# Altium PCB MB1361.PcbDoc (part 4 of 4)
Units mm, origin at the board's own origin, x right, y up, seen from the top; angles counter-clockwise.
Board outline 70 x 133.34 mm, 6 copper layers (Top Layer, Signal Layer 1, Signal Layer 2, Signal Layer 3, Signal Layer 4, Bottom Layer), stack 1.578 mm thick; 268 components, 251 nets, 1066 pads, 705 vias.
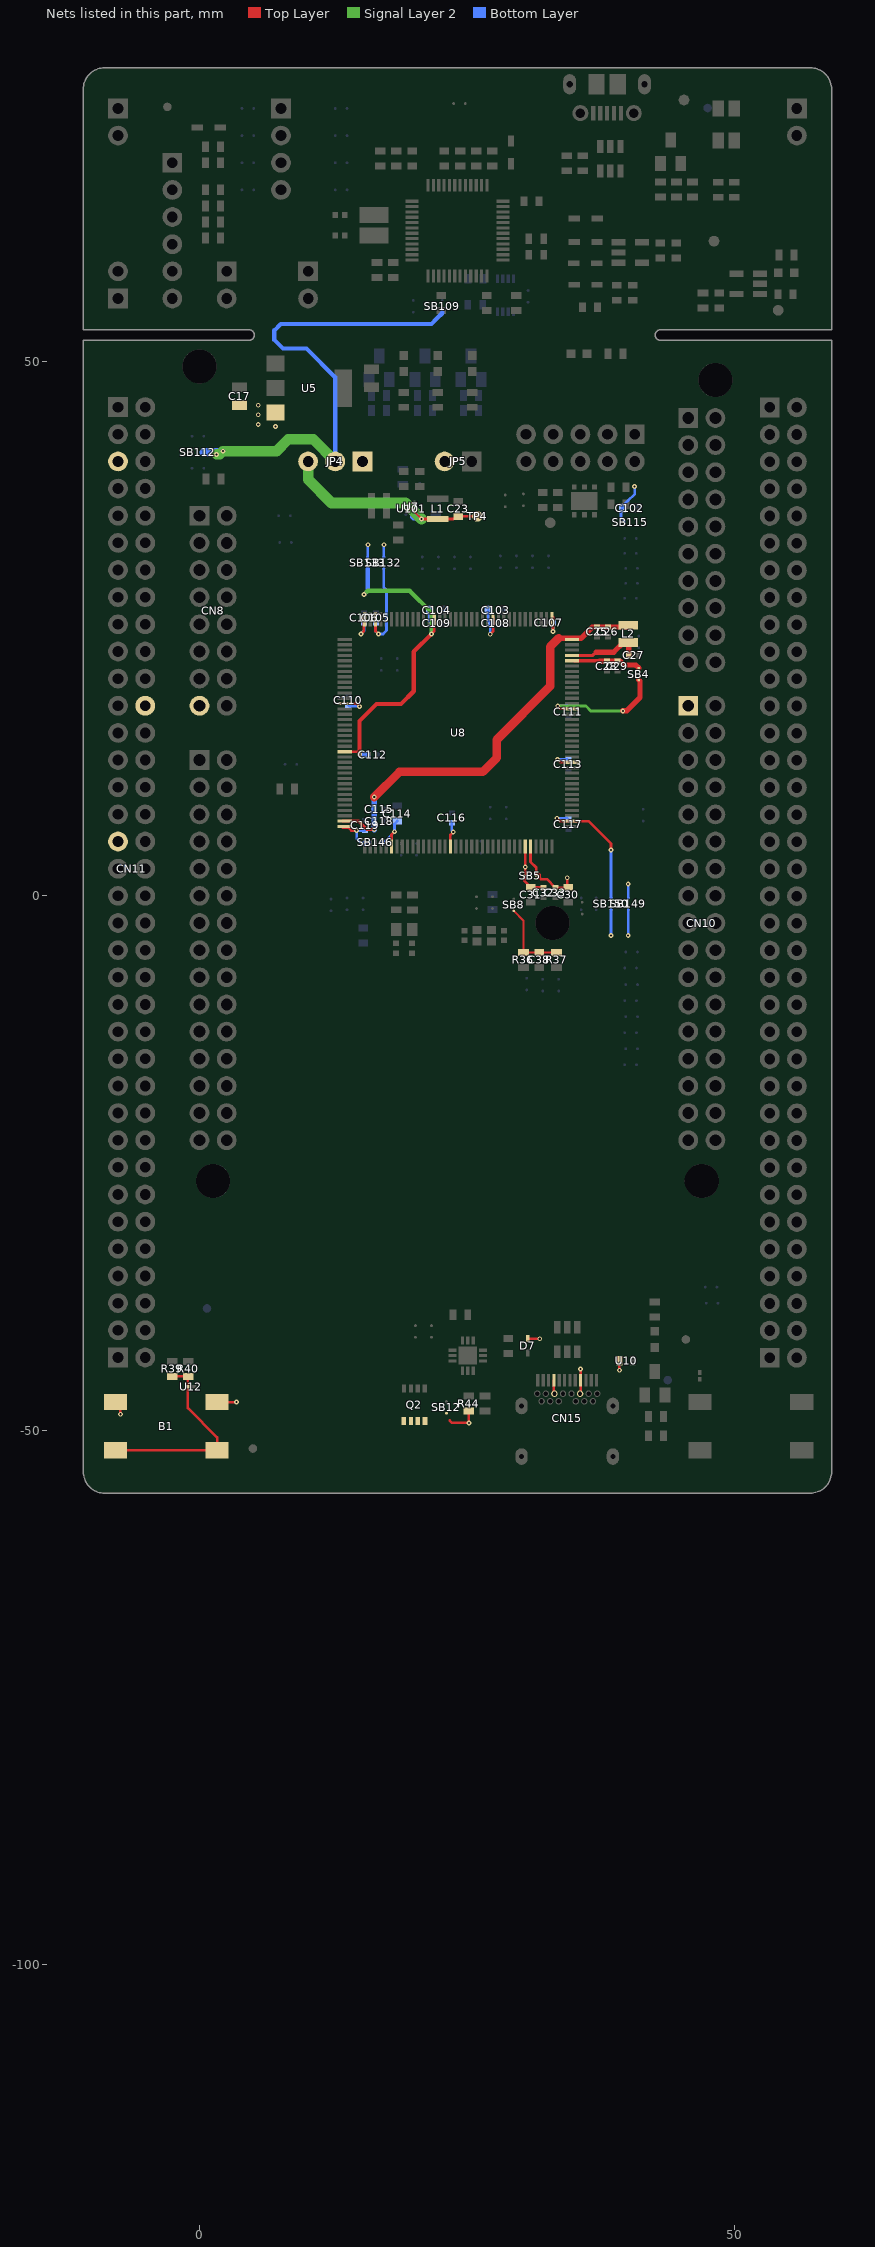
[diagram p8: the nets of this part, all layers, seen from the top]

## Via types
v1: diameter 0.45, hole 0.2, Top Layer to Bottom Layer, tented both sides, 705 vias

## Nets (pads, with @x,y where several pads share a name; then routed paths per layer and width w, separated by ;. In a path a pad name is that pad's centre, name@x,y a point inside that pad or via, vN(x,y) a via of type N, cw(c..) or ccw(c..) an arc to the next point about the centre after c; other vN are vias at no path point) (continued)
USER_BUTTON: B1.3 B1.4 R39.2 R40.2 U12.1 | length 19
  Top Layer w0.25: B1.3@-7.849,-51.856 B1.4@1.651,-51.856 1.651,-50.651 -1.087,-47.913 -1.087,-45.9 -1.087,-44.987 R40.2@-1.05,-44.95 -2.537,-44.95 R39.2@-2.54,-44.947
V15_COUT: C25.2 C26.2 C115.2 C118.2 L2.1 U8.72 U8.143 | length 39.9
  Top Layer w0.3: U8.143@13.392,6.99 U8.143@13.592,6.99 14.91,6.99 15.7,6.2 v1(16.35,6.2)
  Top Layer w0.5: 33.59,24.09 35.69,24.09 36.75,25.15 C25.2@37.2,25.15 C26.2@38.2,25.15 40,25.15 L2.1@40.1,25.25
  Top Layer w0.8: v1(16.35,9.25) 18.7,11.6 26.5,11.6 27.8,12.9 27.8,14.6 32.8,19.6 32.8,23.3 33.59,24.09
  Bottom Layer w0.5: v1(16.35,6.2) C118.2@16.35,7 C115.2@16.35,8.1 v1(16.35,9.25)
VBAT: C114.2 CN11.33 SB146.2 U8.6 | length 4.5
  Top Layer w0.25: U8.6@17.967,4.44 17.967,5.738 v1(18.234,6.005)
  Bottom Layer w0.127: SB146.2@17,5 17.3,5
  Bottom Layer w0.2: 17.3,5 17.3,5.071 v1(18.234,6.005)
  Bottom Layer w0.25: v1(18.234,6.005) 18.234,6.734 C114.2@18.5,7
VBUS_SENSE: C38.2 R36.2 R37.1 SB8.2 | length 7.4
  Top Layer w0.2: SB8.2@29.4,-1.4 30.3,-2.3 R36.2@30.3,-5.3 C38.2@31.8,-5.3 R37.1@33.4,-5.3
VBUSc: CN15.A4 CN15.A9 CN15.B4 CN15.B9 D7.1 Q2.5 Q2.6 Q2.7 Q2.8 R44.2 SB12.2 U10.1 | length 8.6
  Top Layer w0.25: 23.4,-49.075 23.625,-49.3 v1(25.2,-49.3) R44.2@25.2,-48.2 ; D7.1@30.7,-41.425 v1(31.825,-41.425) ; CN15.A4@33.15,-45.32 33.15,-46.52 CN15.B9@33.2,-46.57 ; CN15.B4@35.6,-46.57 35.65,-46.52 CN15.A9@35.65,-45.32 v1(35.65,-44.25) ; v1(39.275,-44.375) U10.1@39.275,-43.5
VDD: CN11.5 JP4.1 JP5.2 SB132.1 SB133.1 SB149.1 | length 3.6
  Bottom Layer w0.25: SB133.1@15.75,31.7 v1(15.75,32.85) ; SB132.1@17.25,31.7 v1(17.25,32.85) ; SB149.1@40.1,-0.2 v1(40.1,1.1)
VDD_MCU: B1.1 B1.2 C103.2 C106.2 C107.2 C108.2 C110.2 C111.2 C113.2 C116.2 C117.2 C119.2 JP4.2 SB4.1 SB109.2 SB112.1 SB146.1 SB150.1 U8.17 U8.38 U8.49 U8.59 U8.73 U8.84 U8.108 U8.121 U8.144 | length 96.2
  Top Layer w0.25: B1.1@-7.849,-47.356 -7.4,-47.805 v1(-7.4,-48.5) ; B1.2@1.651,-47.356 v1(3.446,-47.356) ; U8.144@13.392,6.39 13.927,6.39 14.217,6.1 v1(14.7,6.1) ; U8.121@13.392,17.99 U8.121@13.592,17.99 14.69,17.99 v1(14.957,17.723) ; v1(15.1,24.5) 15.367,24.767 U8.108@15.367,26.065 ; U8.17@23.467,4.415 U8.17@23.467,4.615 23.467,5.713 v1(23.734,5.98) ; v1(27.2,24.475) 27.467,24.742 U8.84@27.467,26.04 ; v1(33.067,24.733) U8.73@33.067,26.065 ; v1(33.452,7.257) 33.719,6.99 U8.38@35.017,6.99 ; v1(33.492,12.757) 33.759,12.49 U8.49@35.057,12.49 ; v1(33.517,17.757) 33.784,17.49 U8.59@34.842,17.49 U8.59@35.082,17.49 ; U8.38@35.042,6.99 36.41,6.99 38.5,4.9 v1(38.5,4.3)
  Top Layer w0.5: v1(39.6,17.3) 39.951,17.3 41.202,18.551 41.202,20.098 SB4.1@41.1,20.2
  Signal Layer 2 w0.25: v1(33.517,17.757) 36.143,17.757 36.6,17.3 v1(39.6,17.3)
  Signal Layer 2 w1: v1(1.6,41.3) 1.9,41.3 v1(2.2,41.6) 7.2,41.6 8.3,42.7 10.64,42.7 JP4.2@12.7,40.64
  Bottom Layer w0.25: C110.2@13.9,17.85 14.027,17.723 v1(14.957,17.723) ; v1(15.1,24.5) 15.4,24.8 C106.2@15.4,25.55 ; C119.2@15.5,6.15 15.45,6.1 v1(14.7,6.1) 14.7,5.357 15.057,5 SB146.1@15.9,5 ; C116.2@23.6,6.85 23.6,6.114 v1(23.734,5.98) ; C103.2@27,26.7 27,25.75 C108.2@27.25,25.5 27.2,25.45 v1(27.2,24.475) ; v1(33.067,24.733) 33.067,25.524 C107.2@33.098,25.555 ; v1(33.452,7.257) 34.393,7.257 C117.2@34.5,7.15 ; v1(33.492,12.757) 34.393,12.757 C113.2@34.5,12.65 ; v1(33.517,17.757) 34.393,17.757 C111.2@34.5,17.65 ; SB150.1@38.5,-0.2 v1(38.5,4.3)
  Bottom Layer w0.4: JP4.2@12.7,40.64 12.7,48.5 10,51.2 7.8,51.2 7,52 7,52.9 7.6,53.5 21.7,53.5 22.2,54 22.7,54.5 SB109.2@22.7,54.6
  Bottom Layer w0.8: SB112.1@0.4,41.5 v1@2.1,41.5
VDD_SMPS_1V8: C23.2 JP4.3 L1.2 TP4.1 U7.E3 U101.C2 | length 21.5
  Top Layer w0.152: L1.2@22.097,35.357 22.145,35.405 L1.2@22.181,35.44
  Top Layer w0.2: U7.E3@20.124,35.9 v1(20.774,35.25)
  Top Layer w0.25: v1(20.774,35.25) L1.2@22.3,35.25 23.75,35.25 24,35.5 C23.2@24.2,35.5 TP4.1@26,35.5
  Signal Layer 2 w1: JP4.3@10.16,40.64 10.16,38.94 12.352,36.748 19.276,36.748 v1(20.774,35.25)
  Bottom Layer w0.25: U101.C2@19.8,35.7 19.8,35.425 19.975,35.25 v1(20.774,35.25)
VDD_USB: C105.2 SB132.2 U8.106 | length 9.6
  Top Layer w0.25: U8.106@16.467,26.065 U8.106@16.467,25.865 16.467,24.767 v1(16.734,24.5)
  Bottom Layer w0.25: C105.2@16.5,25.55 16.5,24.734 v1(16.734,24.5) 17.181,24.5 17.5,24.819 17.5,28.6 17.25,28.85 SB132.2@17.25,30.6
VDDA: C30.1 C33.2 CN10.1 SB5.1 SB149.2 SB150.2 U8.32 | length 11.9
  Top Layer w0.25: U8.32@30.967,4.415 30.967,3.172 31.5,2.639 SB5.1@31.5,1.9 ; 31.8,2 31.8,1.7 31.937,1.562 32.487,1.562 C33.2@33.3,0.75 34.45,0.75 C30.1@34.5,0.8 34.4,0.9 v1(34.4,1.7)
  Bottom Layer w0.25: v1(38.5,-3.7) SB150.2@38.5,-1.3 ; v1(40.1,-3.7) SB149.2@40.1,-1.3
VDDIO: C104.2 C109.2 C112.2 SB133.2 U8.95 U8.130 | length 33.6
  Top Layer w0.25: U8.130@13.392,13.49 U8.130@13.592,13.49 14.957,13.49 ; v1(21.7,24.5) 21.967,24.767 U8.95@21.967,25.865 U8.95@21.967,26.065
  Top Layer w0.4: v1(14.957,13.223) 14.957,13.49 14.957,16.357 16.554,17.954 18.854,17.954 20.046,19.146 20.046,22.846 v1(21.7,24.5)
  Signal Layer 2 w0.4: v1(15.4,28.2) 15.744,28.544 19.656,28.544 21.7,26.5 v1(21.7,24.5)
  Bottom Layer w0.25: C104.2@21.5,26.7 21.5,25.75 C109.2@21.75,25.5 21.7,25.45 v1(21.7,24.5)
  Bottom Layer w0.4: v1(14.957,13.223) 15.727,13.223 C112.2@15.75,13.2 ; v1(15.4,28.2) 15.75,28.55 SB133.2@15.75,30.6
VDDSMPS_CIN: C28.2 C29.2 SB4.2 U8.68 | length 6.3
  Top Layer w0.3: U8.68@35.042,21.99 35.042,21.992 37.45,21.992
  Top Layer w0.5: 37.45,21.95 C28.2@38.1,21.95 C29.2@39.1,21.95 39.335,21.95 39.685,21.6 40.8,21.6 SB4.2@41.1,21.3
VIN: C17.2 CN8.15 CN11.24 U5.3
  other v1: 7.1,43.9 5.5,44.1 5.5,45 5.5,45.9
VLX: C27.2 L2.2 U8.69 | length 6.9
  Top Layer w0.3: U8.69@35.042,22.49 36.79,22.49 37.1,22.8
  Top Layer w0.5: 37.1,22.8 38.75,22.8 39.7,23.75 40.1,23.75 40.15,23.7 C27.2@40.15,22.5
VREFP: C31.1 C32.2 C102.2 SB5.2 SB115.2 U8.31 | length 9.2
  Top Layer w0.25: U8.31@30.467,4.415 v1(30.467,2.7) 30.467,1.967 SB5.2@30.4,1.9 30.4,1.4 C31.1@31,0.8 32.15,0.8 C32.2@32.2,0.75
  Bottom Layer w0.25: SB115.2@39.767,34.936 39.767,35.015 39.423,35.359 39.423,36.093 C102.2@39.567,36.236 39.567,36.467 40.063,36.963 40.098,36.963 40.7,37.565 v1(40.7,38.3)
pads on no net: CN11.10 CN11.26 CN11.67 CN11.70 CN12.6 CN12.16 CN12.34 CN15.A2 CN15.A3 CN15.A8 CN15.A10 CN15.A11 CN15.B2 CN15.B3 CN15.B8 CN15.B10 CN15.B11 Designator1.1 Designator3.1 Designator4.1 Designator100.1 Designator102.1 Designator103.1 U2.4 U2.11 U2.14 U2.16 U2.17 U2.19 U2.21 U2.22 U2.40 U2.41 U2.42 U2.43 U2.45 U2.46 U6.3 U6.5 U7.E1 U9.5 U101.C1

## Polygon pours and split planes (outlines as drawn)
GND on Top Layer "GND" (solid, remove dead copper, pour order 342): -10.946,-53.804 ccw(c-8.946,-53.804) -8.946,-55.804 -8.946,-55.805 1.143,-55.805 26.426,-55.805 57.05,-55.805 ccw(c57.05,-53.805) 59.05,-53.805 59.05,-53.8 59.054,-53.8 59.054,75.536 ccw(c57.054,75.536) 57.054,77.536 -8.946,77.536 ccw(c-8.946,75.536) -10.946,75.536 -10.946,-53.804
5V_USB_STLK on Top Layer "5V_USB_STLK" (solid, pour order 302): 38.953,74.679 39.185,74.911 43.315,74.911 43.547,74.679 43.547,72.987 42.371,71.811 39.159,71.811 39.151,71.802 38.953,72
5V_USB_STLK on Top Layer "5V_USB_STLK" (solid, pour order 320): 51,56.675 50.375,57.3 45.1,57.3 44.5,56.7 44.5,54.9 44.7,54.7 45.883,54.7 46.1,54.917 46.1,55.15 46.35,55.4 50.675,55.4 51,55.725
VIN on Top Layer "V_IN" (solid, pour order 324): 2.828,46.9 4.8,46.9 5.2,46.5 8.4,46.5 8.8,46.1 8.8,44 8.4,43.6 3,43.6 2.4,44.2 2.4,46.5
5V on Top Layer "5V" (solid, pour order 328): 29.45,42.05 41.665,42.05 42.35,41.365 42.35,39.75 41.65,39.05 39.65,39.05 39.35,38.75 39.35,35.55 38.75,34.95 36.549,34.95 36.4,35.099 36.4,38.8 36.25,38.95 29.65,38.95 29.05,39.55 29.05,41.65
NetC21_2 on Top Layer "Net_C19_2" (solid, pour order 330): 35.3,34.6 35.3,36.4 34.52,37.18 29.767,37.18 29.537,36.95 29.537,35.063 30.7,33.9 34.6,33.9
VDD_MCU on Signal Layer 3 "VDD_MCU" (solid, pour order 382): 18.1,42.6 18.4,42.6 cw(c18.4,41.8) 19.2,41.8 19.2,36.4 ccw(c19.8,36.4) 19.8,35.8 32.846,35.8 cw(c32.846,35.046) 33.6,35.046 33.6,20.4 ccw(c34.2,20.4) 34.2,19.8 34.317,19.8 cw(c34.317,19.417) 34.7,19.417 34.7,7.6 cw(c33.922,7.622) 33.9,6.843 26.253,6.843 ccw(c26.261,6.382) 25.8,6.375 25.8,3.4 25.8,-42.3 cw(c25.4,-42.3) 25.4,-42.7 5.1,-42.7 ccw(c5.1,-43.7) 4.1,-43.7 4.1,-48.3 cw(c3.6,-48.3) 3.6,-48.8 -7.9,-48.8 cw(c-7.9,-48.3) -8.4,-48.3 -8.4,-46.9 cw(c-7.9,-46.9) -7.9,-46.4 1.9,-46.4 ccw(c1.9,-46) 2.3,-46 2.3,-41.9 cw(c3.3,-41.9) 3.3,-40.9 22,-40.9 ccw(c22,-40.2) 22.7,-40.2 22.7,-1.8 ccw(c21.5,-1.8) 21.5,-0.6 19.8,-0.6 cw(c19.8,0.6) 18.6,0.6 18.6,3.2 18.6,6.4 ccw(c18.1,6.4) 18.1,6.9 15.4,6.9 ccw(c15.4,6.6) 15.1,6.6 15.1,6 cw(c14.657,6) 14.657,5.557 14.623,5.557 12.49,5.431 cw(c12.49,6.221) 11.7,6.221 11.7,42.01 cw(c12.29,42.01) 12.29,42.6
5V_UCPD on Signal Layer 3 "5V_USB_TYPEC" (solid, pour order 388): 30.35,-36.15 30.35,-45.35 cw(c29.4,-45.35) 29.4,-46.3 19.9,-46.3 cw(c19.9,-45.4) 19,-45.4 19,-44 cw(c19.9,-44) 19.9,-43.1 25.3,-43.1 ccw(c25.3,-42.3) 26.1,-42.3 26.1,6.199 cw(c26.541,6.199) 26.54,6.64 34.317,6.64 ccw(c34.337,7.403) 35.1,7.383 35.1,19.59 ccw(c34.59,19.59) 34.59,20.1 34.2,20.1 cw(c34.2,20.5) 33.8,20.5 33.8,35.4 cw(c34.2,35.4) 34.2,35.8 36.6,35.8 cw(c36.6,35.4) 37,35.4 37,5.2 cw(c36.284,5.184) 36.3,4.469 30.467,4.469 29.969,4.469 ccw(c29.969,4.2) 29.7,4.2 29.7,3.2 29.7,-4.648 ccw(c30,-4.648) 30,-4.948 cw(c30,-5.248) 30.3,-5.248 30.3,-5.5 30.3,-35.253 30.3,-36.1
VREFP on Signal Layer 3 "VREFP" (solid, remove dead copper, pour order 358): 41.3,39.2 cw(c41.3,38.9) 41.6,38.9 41.6,35.2 ccw(c42,35.2) 42,34.8 42.683,34.8 cw(c42.683,34.383) 43.1,34.383 43.1,29.4 cw(c42.5,29.4) 42.5,28.8 ccw(c42.5,28.2) 41.9,28.2 41.9,20.9 cw(c41.5,20.9) 41.5,20.5 40.95,20.5 ccw(c40.95,19.65) 40.1,19.65 40.1,3.4 cw(c39.2,3.4) 39.2,2.5 38.3,2.5 34,2.5 ccw(c34,2.1) 33.6,2.1 33.6,1.9 cw(c33.392,1.9) 33.392,1.692 30.3,1.692 cw(c30.3,1.992) 30,1.992 30,3.8 cw(c30.313,3.813) 30.3,4.126 36.3,4.126 36.426,4.126 ccw(c36.426,5) 37.3,5 37.3,34.1 cw(c37.8,34.1) 37.8,34.6 39.9,34.6 ccw(c39.868,35.068) 40.335,35.1 40.335,38.835 cw(c40.7,38.835) 40.7,39.2
3V3_STLK on Signal Layer 3 "ST_3V3" (solid, remove dead copper, pour order 346): 46.9,63.4 cw(c47.5,63.4) 47.5,64 48,64 52.923,64 ccw(c52.923,64.545) 53.469,64.545 53.469,68.936 ccw(c50.929,68.936) 50.929,71.476 37.795,71.476 cw(c37.795,71.933) 37.338,71.933 37.338,76.76 ccw(c36.957,76.76) 36.957,77.141 -8.509,77.141 -8.509,77.14 -8.966,77.14 ccw(c-8.966,75.565) -10.541,75.565 -10.541,53.518 ccw(c-10.312,53.518) -10.312,53.289 27.445,53.289 ccw(c27.445,53.454) 27.61,53.454 27.61,61.426 cw(c28.185,61.426) 28.185,62.001 36.671,62.001 cw(c36.671,61.683) 36.99,61.683 36.99,60.876 ccw(c37.16,60.876) 36.991,60.859 ccw(c37.45,60.859) 37.449,60.4 46.7,60.4 ccw(c46.7,60.6) 46.9,60.6
3V3 on Signal Layer 3 "3V3" (solid, remove dead copper, pour order 348): 4.191,45.791 cw(c4.9,45.791) 4.9,46.5 8.1,46.5 cw(c8.1,46.1) 8.5,46.1 8.5,45.3 ccw(c8.922,45.278) 8.9,44.856 23,44.856 23.144,44.856 cw(c23.144,44.3) 23.7,44.3 23.7,39.37 ccw(c24.17,39.37) 24.17,38.9 26.3,38.9 ccw(c26.3,39.3) 26.7,39.3 26.7,43 26.7,46.649 ccw(c25.815,46.733) 26.5,47.3 ccw(c25.95,46.821) 25.999,47.549 25.8,47.549 7.8,47.549 cw(c7.8,47.949) 7.4,47.949 7.4,48.9 ccw(c7.1,48.9) 7.1,49.2 3.3,49.2 ccw(c3.3,48.929) 3.029,48.929 3.029,46.837 3.029,46.811 cw(c2.559,46.811) 2.559,46.341 -1.51,46.341 ccw(c-1.51,45.691) -2.159,45.691 -2.159,40.056 cw(c-2.87,40.056) -2.87,39.345 -10.422,39.345 ccw(c-10.422,38.971) -10.795,38.971 -10.795,27.381 ccw(c-10.135,27.381) -10.135,26.721 3.668,26.721 ccw(c3.668,27.244) 4.191,27.244
5V_EXT on Signal Layer 3 "5V_EXT" (solid, remove dead copper, pour order 352): 2.845,48.945 cw(c3.3,48.945) 3.3,49.4 7.3,49.4 cw(c7.3,49.1) 7.6,49.1 7.6,48.2 ccw(c8.099,48.201) 8.1,47.701 26.314,47.701 cw(c26.315,47.015) 26.8,47.5 cw(c26.319,47.018) 27,47.017 27,42.464 27,39.4 ccw(c27.5,39.4) 27.5,38.9 38.475,38.9 ccw(c38.475,39.325) 38.9,39.325 38.9,51.4 ccw(c38.7,51.4) 38.7,51.6 32.8,51.6 ccw(c32.8,51.4) 32.6,51.4 32.6,41.672 cw(c32.028,41.672) 32.028,41.1 29.78,41.1 cw(c29.78,41.98) 28.9,41.98 28.9,49.2 cw(c29.2,49.2) 29.2,49.5 ccw(c29.2,49.773) 29.473,49.773 29.473,51.1 29.444,59.079 cw(c30.201,59.079) 30.201,59.835 36.525,59.835 ccw(c36.525,60.14) 36.83,60.14 36.83,61.54 ccw(c36.521,61.54) 36.521,61.849 28.389,61.849 ccw(c28.389,61.29) 27.83,61.29 27.83,52.011 cw(c27.711,52.011) 27.711,51.892 -10.363,51.892 ccw(c-10.363,51.46) -10.795,51.46 -10.795,39.937 ccw(c-10.355,39.937) -10.355,39.497 -2.979,39.497 ccw(c-2.979,40.175) -2.302,40.175 -2.302,45.788 cw(c-1.607,45.788) -1.607,46.482 2.413,46.482 ccw(c2.413,46.914) 2.845,46.914
VBAT on Signal Layer 3 "VBAT" (solid, remove dead copper, pour order 356): 11.038,10.77 cw(c11.038,10.521) 11.287,10.521 11.287,5.872 ccw(c11.885,5.859) 11.873,5.261 14.428,5.3 15,5.3 ccw(c15,5.624) 15.324,5.624 15.324,6.579 cw(c15.415,6.579) 15.415,6.669 17.983,6.669 cw(c17.983,6.265) 18.387,6.265 18.387,0.965 cw(c17.676,0.965) 17.676,0.254 -10.338,0.254 cw(c-10.338,0.66) -10.744,0.66 -10.744,10.39 cw(c-10.364,10.39) -10.364,10.77
VIN on Signal Layer 3 "VIN" (solid, remove dead copper, pour order 360): 8,45.7 ccw(c7.5,45.7) 7.5,46.2 5.1,46.2 ccw(c5.1,45.5) 4.4,45.5 4.4,43.3 4.435,34.2 4.435,22.665 cw(c3.97,22.665) 3.97,22.2 -6.1,22.2 ccw(c-6.1,21.6) -6.7,21.6 -6.7,16.082 ccw(c-6.108,16.082) -6.108,15.49 7.5,15.49 ccw(c7.495,15.995) 8,16
VDDA on Signal Layer 3 "AVDD" (solid, remove dead copper, pour order 362): 40.4,18.1 40.4,19 cw(c41,19) 41,19.6 48.837,19.6 cw(c48.837,19.037) 49.4,19.037 49.4,17.2 cw(c48.982,17.182) 49,16.764 43.264,16.764 ccw(c43.264,16.2) 42.7,16.2 42.7,-3.4 cw(c41.95,-3.45) 42,-4.2 34.4,-4.2 cw(c34.4,-3.6) 33.8,-3.6 33.8,1.904 cw(c34.2,1.904) 34.2,2.304 39.8,2.304 ccw(c39.802,2.902) 40.4,2.9
AGND on Signal Layer 3 "AGND" (solid, remove dead copper, pour order 364): 39.1,-38.8 40.8,-38.8 cw(c40.8,-39.6) 41.6,-39.6 41.6,-42.1 cw(c41.55,-42.15) 41.6,-42.2 41.6,-55.1 ccw(c42.2,-55.1) 42.2,-55.7 42.6,-55.677 57.074,-55.677 ccw(c57.074,-53.873) 58.877,-53.873 58.877,33.35 ccw(c58.145,33.352) 58.876,33.399 58.876,35.363 ccw(c58.206,35.431) 58.273,36.1 44,36.1 43.7,36.1 cw(c43.7,36.7) 43.1,36.7 43.1,38.923 ccw(c42.823,38.923) 42.823,39.2 42,39.2 ccw(c42,39) 41.8,39 41.8,35.4 ccw(c42.1,35.4) 42.1,35.1 42.739,35.1 cw(c42.767,34.611) 43.256,34.639 43.256,29.356 cw(c42.6,29.356) 42.6,28.7 ccw(c42.6,28.3) 42.2,28.3 42.2,20.4 ccw(c42.957,20.4) 42.957,19.643 49.247,19.643 cw(c49.247,19.2) 49.69,19.2 49.69,17.09 cw(c49.197,17.086) 49.2,16.593 47,16.593 43.393,16.593 ccw(c43.393,16.2) 43,16.2 43,-4.2 cw(c42.625,-4.175) 42.6,-4.549 31.214,-4.549 ccw(c31.214,-5.08) 30.683,-5.08 30.683,-37.583 ccw(c31.9,-37.583) 31.9,-38.8
5V_STLK on Signal Layer 3 "5V_STLK" (solid, remove dead copper, pour order 366): 43.41,38.874 43.41,39.19 ccw(c42.9,39.19) 42.9,39.7 40,39.7 cw(c40,40.4) 39.3,40.4 39.3,53.3 cw(c40.303,53.3) 39.301,53.34 39.301,54.401 cw(c39.6,54.401) 39.6,54.7 50,54.7 ccw(c50,55.3) 50.6,55.3 50.6,60.665 cw(c51.035,60.665) 51.035,61.1 51.1,61.1 58.776,61.102 58.776,37.076 cw(c58.1,37.076) 58.1,36.4 44.169,36.4 cw(c44.169,37.159) 43.41,37.159
5V_USB_STLK on Signal Layer 3 "5V_USB_STLK" (solid, pour order 380): 32.4,45.1 32.4,52.8 cw(c32.8,52.8) 32.8,53.2 38.4,53.2 ccw(c38.4,53.9) 39.1,53.9 39.1,54.477 cw(c39.423,54.477) 39.423,54.8 47.96,54.8 ccw(c47.96,57.297) 48,54.8 49.6,54.8 ccw(c49.6,55.7) 50.5,55.7 50.5,60.9 cw(c50.9,60.9) 50.9,61.3 58.6,61.3 ccw(c58.6,61.4) 58.7,61.4 58.7,75.3 ccw(c57,75.3) 57,77 37.7,77 ccw(c37.7,76.9) 37.6,76.9 37.6,72.1 ccw(c37.9,72.1) 37.9,71.8 53,71.8 cw(c53,71.1) 53.7,71.1 53.7,64.4 cw(c53.1,64.4) 53.1,63.8 47.7,63.8 ccw(c47.7,63.3) 47.2,63.3 47.2,60.7 cw(c46.7,60.7) 46.7,60.2 37.8,60.2 37.1,59.5 30.3,59.5 ccw(c30.3,58.9) 29.7,58.9 29.7,49.5 cw(c29.4,49.5) 29.4,49.2 ccw(c29.4,48.85) 29.05,48.85 29.05,42.14 ccw(c29.89,42.14) 29.89,41.3 31.937,41.3 ccw(c31.937,41.763) 32.4,41.763
5V on Signal Layer 3 "5V" (solid, pour order 384): 18.7,42.9 18.9,42.9 cw(c18.9,42.3) 19.5,42.3 19.5,36.7 ccw(c20.1,36.7) 20.1,36.1 37,36.1 cw(c37,35.8) 37.3,35.8 37.3,35.19 ccw(c37.59,35.19) 37.59,34.9 39.7,34.9 ccw(c39.7,35.3) 40.1,35.3 40.1,36.763 40.1,37.9 ccw(c39.3,37.9) 39.3,38.7 23.7,38.7 cw(c23.7,39) 23.4,39 23.4,43.9 ccw(c22.8,43.9) 22.8,44.5 8.852,44.5 ccw(c8.852,43.948) 8.3,43.948 8.3,15.7 cw(c7.7,15.7) 7.7,15.1 -6.24,15.1 cw(c-6.24,15.86) -7,15.86 -7,22 cw(c-6.6,22) -6.6,22.4 3.6,22.4 ccw(c3.6,23) 4.2,23 4.2,26.1 ccw(c3.8,26.1) 3.8,26.5 -9.9,26.5 ccw(c-9.9,26) -10.4,26 -10.4,14.195 -10.474,11.729 ccw(c-9.816,11.729) -9.816,11.071 11.074,11.071 ccw(c11.074,11.398) 11.4,11.398 11.4,42.3 cw(c12,42.3) 12,42.9
GND on Signal Layer 3 "GND" (solid, pour order 390): 17.9,0 cw(c17.9,-0.2) 18.1,-0.2 ccw(c18.9,-0.2) 18.9,-1 21.6,-1 cw(c21.6,-1.7) 22.3,-1.7 22.3,-40 cw(c21.8,-40) 21.8,-40.5 2.9,-40.5 ccw(c2.9,-41.5) 1.9,-41.5 1.9,-45.4 cw(c1.3,-45.4) 1.3,-46 -7.9,-46 ccw(c-7.9,-46.9) -8.8,-46.9 -8.8,-48.2 ccw(c-7.9,-48.2) -7.9,-49.1 3.7,-49.1 ccw(c3.7,-48.3) 4.5,-48.3 4.5,-43.7 cw(c5.2,-43.7) 5.2,-43 18.4,-43 cw(c18.4,-43.3) 18.7,-43.3 18.7,-55 cw(c18.2,-55) 18.2,-55.5 -8.9,-55.5 cw(c-8.9,-53.8) -10.6,-53.8 -10.6,-0.4 cw(c-10.2,-0.4) -10.2,0
VBUSc on Signal Layer 3 "VBUSc" (solid, remove dead copper, pour order 392): 31.4,-39.2 40.2,-39.2 cw(c40.2,-40.3) 41.3,-40.3 41.3,-55.2 cw(c40.8,-55.2) 40.8,-55.7 19.5,-55.7 cw(c19.5,-55.2) 19,-55.2 19,-47.2 cw(c19.4,-47.2) 19.4,-46.8 29.8,-46.8 ccw(c29.8,-45.8) 30.8,-45.8 30.8,-39.8 cw(c31.4,-39.8)
GND on Signal Layer 2 "GND" (solid, remove dead copper, pour order 372): -10.87,-53.88 ccw(c-8.87,-53.88) -8.87,-55.88 -8.87,-55.881 1.219,-55.881 26.503,-55.881 57.126,-55.881 ccw(c57.126,-53.881) 59.126,-53.881 59.126,-53.876 59.13,-53.876 59.13,75.46 ccw(c57.13,75.46) 57.13,77.46 -8.87,77.46 ccw(c-8.87,75.46) -10.87,75.46 -10.87,-53.88
3V3 on Signal Layer 2 "3V3" (solid, pour order 370): 24.18,42.3 23.8,41.92 23.8,38.58 25.48,36.9 30.5,36.9 31.1,37.5 31.1,38.8 30.6,39.3 29.67,39.3 26.67,42.3
VDD on Signal Layer 4 "VDD" (solid, remove dead copper, pour order 378): -10.87,-53.88 ccw(c-8.87,-53.88) -8.87,-55.88 -8.87,-55.881 1.219,-55.881 26.503,-55.881 57.126,-55.881 ccw(c57.126,-53.881) 59.126,-53.881 59.126,-53.876 59.13,-53.876 59.13,75.46 ccw(c57.13,75.46) 57.13,77.46 -8.87,77.46 ccw(c-8.87,75.46) -10.87,75.46 -10.87,-53.88
5V_VIN on Signal Layer 4 "5V_VIN" (solid, remove dead copper, pour order 376): 14.6,47 38.3,47 39.685,45.615 39.685,42.085 39.265,41.665 37.235,41.665 36.582,42.317 36.582,44.117 35.5,45.2 14.837,45.2 14.3,45.737 14.3,46.7
GND on Bottom Layer "GND" (solid, remove dead copper, pour order 344): -10.769,-53.88 ccw(c-8.769,-53.88) -8.769,-55.88 -8.769,-55.881 1.321,-55.881 26.604,-55.881 57.227,-55.881 ccw(c57.227,-53.881) 59.227,-53.881 59.227,-53.876 59.231,-53.876 59.231,75.46 ccw(c57.231,75.46) 57.231,77.46 -8.769,77.46 ccw(c-8.769,75.46) -10.769,75.46 -10.769,-53.88
GND on Signal Layer 1 "GND" (solid, remove dead copper, pour order 374): -10.87,-53.88 ccw(c-8.87,-53.88) -8.87,-55.88 -8.87,-55.881 1.219,-55.881 26.503,-55.881 57.126,-55.881 ccw(c57.126,-53.881) 59.126,-53.881 59.126,-53.876 59.13,-53.876 59.13,75.46 ccw(c57.13,75.46) 57.13,77.46 -8.87,77.46 ccw(c-8.87,75.46) -10.87,75.46 -10.87,-53.88

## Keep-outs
Keep-Out Layer:
  lines w0.127: -8.874,-55.881 26.416,-55.881 ; -8.87,-55.88 cw(c-8.87,-53.88) -10.87,-53.88 -10.87,51.96 4.63,51.96 ccw(c4.63,52.46) 4.63,52.96 -10.87,52.96 -10.87,75.46 cw(c-8.87,75.46) -8.87,77.46 57.13,77.46 cw(c57.13,75.46) 59.13,75.46 ; 40.589,-55.881 57.126,-55.881 ; 57.126,-55.876 ccw(c57.126,-53.876) 59.126,-53.876 ; 59.13,-53.88 59.13,51.96 43.13,51.96 cw(c43.13,52.46) 43.13,52.96 59.13,52.96 59.13,75.46 ; 59.13,75.46 59.13,75.46 ; 8.13,51.96 cw(c8.13,52.46) 8.13,52.96 27.13,52.96 cw(c27.13,52.46) 27.13,51.96 8.13,51.96 ; 31.75,51.96 cw(c31.75,52.46) 31.75,52.96 39.08,52.96 cw(c39.08,52.46) 39.08,51.96 31.75,51.96

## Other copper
Top Layer:
  rectangle net 5V_UCPD: 34.146,62.395 36.432,63.792
  rectangle net 5V_VIN: 34.036,58.115 36.322,59.512
  rectangle net 3V3_STLK: 40.792,60.604 46.812,61.876
  rectangle net 5V_EXT: 34.061,60.096 36.347,61.493
  rectangle net 5V_USB_STLK: 34.061,56.109 36.347,57.506
  rectangle net 5V_STLK: 50.45,59.25 52.875,60.622
  pour cut-out: 45.085,55.093 45.319,55.093 45.319,55.245 45.085,55.245
  region net VBUSc: 18.875,-47.1 22.05,-47.1 23.1,-48.15 23.6,-47.65 23.6,-49.1 23.05,-49.65 18.533,-49.65 18.15,-49.267 18.15,-47.425 18.475,-47.1
  region net 5V_UCPD: 19.6,-46.4 21.6,-46.4 23.1,-47.9 23.6,-47.4 23.6,-45.9 24.7,-44.8 24.7,-44.15 23.256,-44.15 22.206,-45.2 19.95,-45.2 19.6,-45.55
  text "1" at 40.559,-54.568 h2
  text ".Layer_Name" at -11.916,-114.15 h3
  text ".GTL" at 29.778,-114.15 h3
Signal Layer 1:
  text "2" at 41.809,-54.568 h2
  text ".Layer_Name" at -11.916,-114.15 h3
  text ".G1" at 29.778,-114.15 h3
Signal Layer 2:
  text "3" at 43.309,-54.568 h2
  text ".Layer_Name" at -11.916,-114.15 h3
  text ".G2" at 29.778,-114.15 h3
Signal Layer 3:
  text "4" at 45.559,-54.568 h2
  text ".Layer_Name" at -11.885,-114.133 h3
  text ".G3" at 29.81,-114.133 h3
Signal Layer 4:
  text "5" at 47.059,-54.568 h2
  text ".Layer_Name" at -11.885,-114.133 h3
  text ".G4" at 29.81,-114.133 h3
Bottom Layer:
  text "6" at 48.559,-54.568 h2
  text ".GBL" at 18.575,-114.182 h3
  text ".Layer_Name" at 59.889,-114.182 h3
Multi-Layer:
  pour cut-out: 40.266,-52.971 40.266,-54.971 48.766,-54.971 48.766,-52.971

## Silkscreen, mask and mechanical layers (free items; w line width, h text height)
Top Overlay:
  region: 10.439,74.105 9.677,74.105 9.677,70.663 10.439,70.663
  region: 10.439,69.025 9.677,69.025 9.677,65.583 10.439,65.583
  lines w0.127: -8.89,-44.45 -8.89,-41.859 ; -8.89,45.009 -8.89,46.99 ; -3.81,-44.45 -3.81,-41.859 ; -3.81,45.009 -3.81,46.99 ; -3.1,-16.6 -1.8,-16.6 ; -3.1,-1.5 -1.8,-1.5 ; -3,-21.4 -1.7,-21.4 ; -3,-13.6 -1.7,-13.6 ; -3,-7.1 -1.7,-7.1 ; -3,-6 -1.7,-6 ; 4.1,36.5 6.1,36.5 6.967,36.5 6.967,31.2 ; 4.2,1.4 6.79,1.4 6.79,5.5 ; 4.2,13.7 6.79,13.7 6.79,9.6 ; 4.3,-1.7 7.7,-1.7 7.7,-4.2 ; 4.3,20.9 5.6,20.9 ; 4.3,21.8 5.6,21.8 7,21.8 7,25.8 ; 4.4,-21.1 7.8,-21.1 7.8,-18.6 ; 4.4,-11.7 7.8,-11.7 7.8,-14.7 ; 4.4,-10.9 7.8,-10.9 7.8,-8.4 ; 5,16.99 6.7,16.99 6.7,18.09 ; 5,20.9 6.7,20.9 6.7,19.8 ; 40.7,-6.6 40.7,-13.5 42.8,-13.5 44.1,-13.5 ; 40.7,-3.4 40.7,3.8 42.8,3.8 44.1,3.8 ; 40.7,34.9 42.3,37.5 ; 40.9,-13.5 44.3,-13.5 ; 40.9,28.5 41.6,26 ; 41,6.2 41,4.2 41.1,4.2 43.9,4.2 ; 41,9.1 41,11.1 41.1,11.1 43.9,11.1 ; 41.1,26.3 41.6,26 ; 41.7,37.3 42.3,37.5 ; 41.8,26.6 41.6,26 ; 42.4,36.9 42.3,37.5 ; 43,-22.3 43,-22.6 43,-23.1 44.3,-23.1 ; 43,-18.3 43,-18 43,-17.5 44.3,-17.5 ; 49.7,-23.1 51,-23.1 51,-22.6 51,-22.3 ; 49.7,-2.2 51,-2.2 51,-2.7 51,-3 ; 57.15,-44.475 57.15,-41.885 52.07,-41.885 52.07,-44.475 ; 57.15,44.983 57.15,46.965 ; 52.07,-44.475 52.07,-44.475 ; 4.3,16.99 5.6,16.99 4.3,16.99 ; 25.1,31.2 27,31.2 27,34.2 25.1,34.2 25.1,31.4 25.1,31.2 ; 31.2,30.7 31.2,32.6 31.4,32.6 34.2,32.6 34.2,30.7 31.2,30.7 ; 46.2,57.4 49.4,57.4 49.4,59.7 47,59.7 46.2,59.7 46.2,57.4 ; 46.5,74.8 46.5,76.8 46.7,76.8 53.9,76.8 53.9,74.8 46.5,74.8 ; 55.5,53.3 55.5,55.4 56.1,55.4 56.3,55.6 58.7,55.6 58.7,53.3 55.5,53.3
  lines w0.305: 4.801,65.342 5.563,65.342 5.563,68.758 4.801,68.758 4.801,65.342 ; 4.801,70.663 4.801,74.105 5.563,74.105 5.563,70.663 4.801,70.663
  text "USB_STLK" at 46.8,75.3 h1.02
  text "ON" at 10.563,74.783 h1.02 r90
  text "OFF" at 5.7,74.7 h1.02 r90
  text "GND" at -4.8,71.2 h1.02 r90
  text "GND" at 54.1,71.1 h1.02 r90
  text "COM" at 47.8,68.7 h1.02
  text "ST-LINK" at 4.1,67 h1.02 r90
  text "NUCLEO" at 12,67 h1.02 r90
  text "E" at 51.4,62.2 h12
  text "SWD" at -4.3,61.3 h1.02 r90
  text "STLK_RST" at -7.2,60.5 h0.91 r90
  text "RX" at 12,57.9 h1.02
  text "3V3 / STLK" at 46.4,57.6 h1.27
  text "TX" at 12,55.4 h1.02
  text "T_NRST" at 5.22,54.609 h1.5 r90
  text "5V / STLK" at 55.8,53.5 h1.27
  text "5V_CHGR" at 31.5,44.8 h1.27 r90
  text "5V_USB_C" at 34.6,44.8 h1.27 r90
  text "5V_EXT" at 36.6,44.8 h1.27 r90
  text "5V_VIN" at 39,44.8 h1.27 r90
  text "5V_STLK" at 41.7,44.8 h1.27 r90
  text "MCLK" at 41.3,44.6 h1.27
  text "D15 / SCL" at 50.7,43.8 h1.27 r45
  text "VDD_MCU" at 9.6,42.6 h1.02
  text "IDD" at 23.3,42.5 h1.2
  text "SD" at 42.8,41.8 h1.27
  text "D14 / SDA" at 50.6,41.1 h1.27 r45
  text "5V" at 28.8,39.6 h1.06 r90
  text "SCK" at 42.1,39.2 h1.27
  text "VREFP" at 49.8,38.6 h1.27 r45
  text "3V3" at 14.3,38 h1.02
  text "1V8" at 8.2,37.8 h1.02
  text "FS" at 42.8,36.7 h1.27
  text "GND" at 50.1,36.7 h1.27 r45
  text "D0" at 4.2,35.1 h1.27
  text "NC" at -2.7,34.8 h1.27 r45
  text "D13 / SCK" at 50.5,34.2 h1.27 r45
  text "D1" at 4.1,32.7 h1.27
  text "IOREF" at -3.2,31.9 h1.27 r45
  text "1V8" at 26.6,31.5 h1.02 r90
  text "SAI_C" at 40.6,31.5 h1.27 r90
  text "D12 / MISO" at 50.4,31.5 h1.27 r45
  text "3V3" at 31.5,31.1 h1.02
  text "D2" at 4.2,30.1 h1.27
  text "NRST" at -3.2,29.3 h1.27 r45
  text "MOSI" at 41.6,29 h1.27
  text "D3" at 4.2,27.6 h1.27
  text "SPI_B" at 40.6,27.6 h1.27 r90
  text "D11 / MOSI" at 49.1,27.5 h1.27 r45
  text "3V3" at -3,27 h1.27 r45
  text "SCK" at 42.1,26.5 h1.27
  text "D10 / CS/PWM" at 49.5,25.1 h1.27 r45
  text "CK" at 4.2,25 h1.27
  text "5V" at -2.8,24.7 h1.27 r45
  text "NSS" at 42.1,24 h1.27
  text "D9 / PWM" at 50.2,22.8 h1.27 r45
  text "CMD" at 4.2,22.5 h1.27
  text "SDMMC" at 7.4,22.5 h1.27 r90
  text "MISO" at 41.6,22.2 h1.27
  text "GND" at -3.1,22 h1.27 r45
  text "D8" at 50.3,21.2 h1.27 r45
  text "PF3" at 4,19.8 h1.27
  text "GND" at -3.1,19.1 h1.27 r45
  text "IO" at 7.1,18.5 h1.27 r90
  text "PF5" at 4.046,17.744 h1.27
  text "D7" at 50.4,17.1 h1.27 r45
  text "VIN" at -2.9,16.8 h1.27 r45
  text "AVDD" at 42.2,16.6 h1.27 r45
  text "AGND" at 42.1,13.9 h1.27 r45
  text "D6 / PWM" at 50.3,13.8 h1.27 r45
  text "SCK" at 4.1,12.2 h1.27
  text "A0" at -2.7,12 h1.27 r45
  text "GND" at 42.6,11.6 h1.27 r45
  text "D5 / PWM" at 50.3,11.1 h1.27 r45
  text "RX" at 4.2,9.9 h1.27
  text "A6" at 42.5,9.6 h1.27
  text "A1" at -2.5,9.5 h1.27 r45
  text "D4" at 50.4,9.5 h1.27 r45
  text "A7" at 42.6,7.2 h1.27
  text "TX" at 4.169,7.089 h1.27
  text "A2" at -2.5,6.8 h1.27 r45
  text "ADC" at 41.4,6.4 h1.27 r90
  text "D3 / PWM" at 50.3,5.9 h1.27 r45
  text "USART" at 7.2,5.7 h1.27 r90
  text "RTS" at 4.1,4.7 h1.27
  text "A8" at 42.6,4.7 h1.27
  text "A3" at -2.5,4.3 h1.27 r45
  text "D2" at 50.5,4.1 h1.27 r45
  text "CS" at 42.6,2.2 h1.27
  text "CTS" at 4,2.1 h1.27
  text "A4" at -2.6,1.7 h1.27 r45
  text "D1 / TX" at 50.9,1 h1.27 r45
  text "CLK" at 42.2,-0.275 h1.27
  text "A5" at -2.5,-0.7 h1.27 r45
  text "GND" at 4.6,-1 h1.27 r45
  text "D0 / RX" at 50.9,-1.5 h1.27 r45
  text "1" at -1.5,-2.8 h1.27 r90
  text "MCLK" at 4.13,-3 h1.27
  text "GND" at 41.7,-3 h1.27
  text "2" at -1.4,-5.3 h1.27 r90
  text "IO3" at 42.1,-5.4 h1.27
  text "COMP" at -2.6,-5.5 h1.27 r90
  text "FS" at 4.2,-5.5 h1.27
  text "QSPI" at 41.1,-6.3 h1.27 r90
  text "SCK" at 4.1,-8 h1.27
  text "F" at 9.1,-8 h12
  text "IO1" at 42.2,-8 h1.27
  text "SAI_A" at 8.2,-9.6 h1.27 r90
  text "SD" at 4.2,-10.5 h1.27
  text "IO0" at 42.1,-10.5 h1.27
  text "SCL" at -1.5,-10.6 h1.27 r90
  text "I2C_B" at -2.7,-11.6 h1.27 r90
  text "SD" at 4.3,-13.1 h1.27
  text "IO2" at 42.2,-13.1 h1.27
  text "SDA" at -1.5,-13.4 h1.27 r90
  text "TIMER" at 50.7,-14 h1.27 r90
  text "L" at 8.9,-15.4 h12
  text "SCK" at 4.1,-15.6 h1.27
  text "J" at 16.936,-16 h18
  text "GND" at -3,-16.4 h1.27 r45
  text "GND" at 42.7,-16.5 h1.27 r45
  text "MB1361C" at 18.936,-16.8 h1.02
  text "G" at 29.5,-16.8 h10
  text "MCLK" at 3.9,-18.1 h1.27
  text "RX" at -1.43,-18.5 h1.27 r90
  text "SAI_B" at 8.4,-20.1 h1.27 r90
  text "CAN" at -2.6,-20.2 h1.27 r90
  text "FS" at 4.4,-20.6 h1.27
  text "TX" at -1.43,-21 h1.27 r90
  text "TIMER" at 44.1,-22 h1.27 r90
  text "IO" at -2.5,-23.5 h1.27 r45
  text "IO" at 4.8,-23.5 h1.27 r45
  text "C" at 28.9,-26 h12
  text "I" at 9.9,-26.3 h12
  text "H" at 17.5,-27 h15
  text "USB_5V" at 45,-40.1 h1.02
  text "GND" at -7.5,-45.7 h1.27
  text "GND" at 53.4,-45.7 h1.27
  text "USER" at -4.9,-54.6 h1.02
  text "RESET" at 49.4,-54.7 h1.02
  text "USB1" at 26.2,-54.9 h1.02
  text ".Layer_Name" at -11.916,-114.15 h3
  text ".GTO" at 29.778,-114.15 h3
Bottom Overlay:
  text "PC9" at 51.7,45 h1.27 r315
  text "PC8" at 58.3,44.9 h1.27 r315
  text "PC11" at -2.4,44.5 h1.27 r315
  text "PC10" at -8.9,43.8 h1.27 r315
  text "PB8" at 51.7,42.5 h1.27 r315
  text "PD2" at -2.6,42.3 h1.27 r315
  text "PC6" at 58.2,42.3 h1.27 r315
  text "PC12" at -8.8,41.7 h1.27 r315
  text "NC" at 57.9,40.2 h1.27 r315
  text "PB9" at 51.7,40 h1.27 r315
  text "VDD" at -9.2,39.6 h1.27 r315
  text "5V / EXT" at -2.7,39.4 h1.27 r315
  text "5V / STLK" at 58.4,37.1 h1.27 r315
  text "GND" at -2.4,37 h1.27 r315
  text "VREFP" at 51.9,36.9 h1.27 r315
  text "PH3" at -9,36.7 h1 r315
  text "BOOT0" at -8.9,35.6 h1 r315
  text "NC" at -3,34.9 h1.27 r315
  text "PF6" at -9.3,34.7 h1.27 r315
  text "PD8" at 58.2,34.6 h1.27 r315
  text "GND" at 51.9,34.5 h1.27 r315
  text "PF7" at -9.3,32.3 h1.27 r315
  text "PA12" at 58.3,32.1 h1.27 r315
  text "PA5" at 51.8,31.9 h1.27 r315
  text "IOREF" at -2.1,31.4 h1.27 r315
  text "PA11" at 58.3,29.6 h1.27 r315
  text "PA6" at 51.8,29.4 h1.27 r315
  text "NRST" at -2.3,29.2 h1.27 r315
  text "PA13" at -8.9,29.1 h1.27 r315
  text "NC" at 58,27.2 h1.27 r315
  text "3V3" at -2.7,27.1 h1.27 r315
  text "PA7" at 51.7,26.9 h1.27 r315
  text "PA14" at -8.9,26.6 h1.27 r315
  text "5V" at -2.8,24.6 h1.27 r315
  text "PB11" at 58.4,24.5 h1.27 r315
  text "PB6" at 51.7,24.4 h1.27 r315
  text "PA15" at -8.9,24 h1.27 r315
  text "PC7" at 51.8,21.9 h1.27 r315
  text "GND" at 58.3,21.8 h1.27 r315
  text "GND" at -9.1,21.7 h1.27 r315
  text "GND" at -2.2,21.7 h1.27 r315
  text "GND" at -2.2,19.5 h1.27 r315
  text "PB7" at -9.2,19.4 h1.27 r315
  text "PA9" at 51.7,19.4 h1.27 r315
  text "PB2" at 58.2,19.4 h1.27 r315
  text "PA8" at 51.7,16.9 h1.27 r315
  text "VIN" at -2.3,16.7 h1.27 r315
  text "PB1" at 58.3,16.6 h1.27 r315
  text "PC13" at -8.8,16.3 h1.27 r315
  text "NC" at -2.5,14.6 h1.27 r315
  text "PB15" at 58.3,14.3 h1.27 r315
  text "PB10" at 51.8,14 h1.27 r315
  text "PC14" at -8.9,13.9 h1.27 r315
  text "PB14" at 58.2,11.9 h1.27 r315
  text "PB4" at 51.8,11.7 h1.27 r315
  text "PA0" at -2.3,11.4 h1.27 r315
  text "PC15" at -8.9,11.3 h1.27 r315
  text "PB13" at 58.3,9.3 h1.27 r315
  text "PH0" at -9.2,9.2 h1.27 r315
  text "PB5" at 51.7,9.2 h1.27 r315
  text "PA1" at -2.3,8.9 h1.27 r315
  text "PH1" at -9.3,6.7 h1.27 r315
  text "PB3" at 51.8,6.6 h1.27 r315
  text "AGND" at 58.5,6.5 h1.27 r315
  text "PA4" at -2.3,6.4 h1.27 r315
  text "NC" at 58,4.5 h1.27 r315
  text "PB0" at -2.3,4.4 h1.27 r315
  text "PA10" at 51.8,3.9 h1.27 r315
  text "VBAT" at -8.8,3.7 h1.27 r315
  text "PF5" at 58.3,1.7 h1.27 r315
  text "PC2" at -9.2,1.6 h1.27 r315
  text "PA2" at 51.7,1.6 h1.27 r315
  text "PC1" at -2.3,1.5 h1.27 r315
  text "PC3" at -9.3,-0.8 h1.27 r315
  text "PA3" at 51.7,-1 h1.27 r315
  text "PC0" at -2.3,-1.1 h1.27 r315
  text "PF4" at 58.3,-1.1 h1.27 r315
  text "GND" at 51.86,-3.3 h1.27 r315
  text "PD4" at -9.2,-3.4 h1.27 r315
  text "PE8" at 58.3,-3.4 h1.27 r315
  text "PD3" at -2.3,-3.6 h1.27 r315
  text "PD5" at -9.2,-5.9 h1.27 r315
  text "PF10" at 58.4,-5.9 h1.27 r315
  text "PG2" at -2.3,-6.1 h1.27 r315
  text "PD13" at 51.8,-6.2 h1.27 r315
  text "PD6" at -9.2,-8.4 h1.27 r315
  text "PE7" at 58.2,-8.5 h1.27 r315
  text "PG3" at -2.3,-8.6 h1.27 r315
  text "PD12" at 51.8,-8.7 h1.27 r315
  text "PD7" at -9.3,-10.9 h1.27 r315
  text "PD14" at 58.4,-11 h1.27 r315
  text "PE2" at -2.3,-11.1 h1.27 r315
  text "PD11" at 51.7,-11.3 h1.27 r315
  text "PE3" at -9.2,-13.5 h1.27 r315
  text "PD15" at 58.3,-13.5 h1.27 r315
  text "PE4" at -2.3,-13.6 h1.27 r315
  text "PE10" at 51.8,-14 h1.27 r315
  text "GND" at -9.1,-16 h1.27 r315
  text "PF14" at 58.3,-16 h1.27 r315
  text "PE5" at -2.2,-16.5 h1.27 r315
  text "PE12" at 51.8,-16.5 h1.27 r315
  text "PF1" at -9.3,-18.5 h1.27 r315
  text "PE9" at 58.2,-18.5 h1.27 r315
  text "PF2" at -2.3,-19 h1.27 r315
  text "PE14" at 51.9,-19.2 h1.27 r315
  text "GND" at 58.4,-20.9 h1.27 r315
  text "PF0" at -9.2,-21 h1.27 r315
  text "PF8" at -2.4,-21.4 h1.27 r315
  text "PE15" at 51.8,-21.5 h1.27 r315
  text "PE11" at 58.4,-23.6 h1.27 r315
  text "PD1" at -9.2,-23.7 h1.27 r315
  text "PF9" at -2.6,-23.8 h1.27 r315
  text "PE13" at 51.9,-24.1 h1.27 r315
  text "PD0" at -9.2,-26.1 h1.27 r315
  text "PF3" at 58.2,-26.2 h1.27 r315
  text "PG1" at -2.5,-26.3 h1.27 r315
  text "PF13" at 51.8,-26.4 h1.27 r315
  text "PG0" at -9.2,-28.7 h1.27 r315
  text "PF15" at 58.3,-28.7 h1.27 r315
  text "PF12" at 51.7,-28.9 h1.27 r315
  text "GND" at -2.6,-29 h1.27 r315
  text "PE1" at -9.2,-31.2 h1.27 r315
  text "PF11" at 58.4,-31.3 h1.27 r315
  text "PE6" at -2.5,-31.5 h1.27 r315
  text "PG14" at 51.8,-31.9 h1.27 r315
  text "PG9" at -9.2,-33.8 h1.27 r315
  text "PE0" at 58.4,-34.2 h1.27 r315
  text "PG15" at -2.4,-34.3 h1.27 r315
  text "GND" at 51.8,-34.3 h1.27 r315
  text "PG12" at -8.8,-36.7 h1.27 r315
  text "PG10" at -2.4,-36.7 h1.27 r315
  text "PD10" at 51.8,-36.9 h1.27 r315
  text "PG8" at 58.3,-36.9 h1.27 r315
  text "NC" at -9.2,-38.8 h1.27 r315
  text "PG13" at -2.6,-39.1 h1.27 r315
  text "PG7" at 51.7,-39.1 h1.27 r315
  text "PG5" at 58.4,-39.2 h1.27 r315
  text "NC" at -3.1,-41.1 h1.27 r315
  text "PD9" at -9.2,-41.3 h1.27 r315
  text "PG4" at 51.7,-41.7 h1.27 r315
  text "PG6" at 58.4,-41.9 h1.27 r315
  text "GND" at -2.5,-44.2 h1.27 r315
  text "GND" at 51.7,-44.2 h1.27 r315
  text "GND" at 58.4,-44.2 h1.27 r315
  text "GND" at -9.1,-44.3 h1.27 r315
  text ".GBO" at 18.575,-114.182 h3
  text ".Layer_Name" at 59.889,-114.182 h3
Top Paste:
  text ".Layer_Name" at -11.916,-114.15 h3
  text ".GTP" at 29.778,-114.15 h3
Bottom Paste:
  text ".GBP" at 18.575,-114.182 h3
  text ".Layer_Name" at 59.889,-114.182 h3
Top Solder:
  rectangle: 40.266,-54.971 48.766,-52.971
  text ".Layer_Name" at -11.916,-114.15 h3
  text ".GTS" at 29.778,-114.15 h3
Bottom Solder:
  rectangle: 40.266,-54.971 48.766,-52.971
  text ".GBS" at 18.575,-114.182 h3
  text ".Layer_Name" at 59.889,-114.182 h3
M1-Board Shape:
  lines w0.127: -10.87,-53.88 -10.87,51.96 4.63,51.96 ccw(c4.63,52.46) 4.63,52.96 -10.87,52.96 -10.87,75.46 cw(c-8.87,75.46) -8.87,77.46 57.13,77.46 cw(c57.13,75.46) 59.13,75.46 59.13,75.46 59.13,52.96 43.13,52.96 ccw(c43.13,52.46) 43.13,51.96 59.13,51.96 59.13,-53.88 ; -10.866,-53.879 ccw(c-8.866,-53.879) -8.866,-55.879 ; -8.87,-55.88 57.13,-55.88 ; 57.13,-55.875 ccw(c57.13,-53.875) 59.13,-53.875 ; 8.13,51.96 cw(c8.13,52.46) 8.13,52.96 27.13,52.96 cw(c27.13,52.46) 27.13,51.96 8.13,51.96 ; 31.75,51.96 cw(c31.75,52.46) 31.75,52.96 39.08,52.96 cw(c39.08,52.46) 39.08,51.96 31.75,51.96
M2-Board Dimensions:
  text ".Layer_Name" at -11.916,-114.15 h3
  text ".GM2" at 29.778,-114.15 h3
M14-Top Assembly:
  text ".Layer_Name" at -11.916,-114.15 h3
  text ".GM14" at 29.778,-114.15 h3
M15-Bottom Assembly:
  text ".GM15" at 18.575,-114.182 h3
  text ".Layer_Name" at 59.889,-114.182 h3
Drill Drawing:
  drawing of 484 lines, arcs and shapes, not listed
  text "THE COMPONENTS WITH PLATED THROUGH HOLE (PTH) MAY BE WELDED (CABLED) IN \"PIN-IN-PASTE\" MODE (IF NECESSARY)" at 74.4,124 h3
  text "PCB SPECIFICATIONS :" at 83.561,113.244 h3
  text "A.   MATERIAL :" at 83.561,109.244 h3
  text "FR-4" at 122.061,109.244 h3
  text "TG-170" at 138.561,109.244 h3
  text "X  TG-150" at 156.811,109.244 h3
  text "TG-140" at 172.811,109.244 h3
  text "B.   MATERIAL FAMILY :" at 83.561,106.244 h3
  text "N/A" at 122.061,106.244 h3
  text "C.   SOLDERMASK COLOR :" at 83.561,103.244 h3
  text "GREEN" at 122.061,103.244 h3
  text "X  WHITE" at 138.561,103.244 h3
  text "RED" at 156.811,103.244 h3
  text "BLACK" at 172.811,103.244 h3
  text "D.   SILKSCREEN COLOR :" at 83.561,100.244 h3
  text "WHITE" at 122.061,100.244 h3
  text "YELLOW" at 138.561,100.244 h3
  text "BLACK" at 156.811,100.244 h3
  text "X  Blue ink PANTONE 2955" at 172.811,100.244 h3
  text "E.   SURFACE FINISH :" at 83.561,97.244 h3
  text "X  ENIG" at 122.061,97.244 h3
  text "IMMERSION SILVER" at 138.561,97.244 h3
  text "IMMERSION TIN" at 172.811,97.244 h3
  text "HASL" at 122.061,94.244 h3
  text "HASL (PB-FREE)" at 138.561,94.244 h3
  text "GOLDEN FINGER" at 172.811,94.244 h3
  text "F.   IMPEDANCE CONTROL :" at 83.561,91.244 h3
  text "NO" at 122.061,91.244 h3
  text "X  YES  (SEE IMPEDANCE TABLE FOR DETAIL INFORMATION)" at 138.561,91.244 h3
  text "G.   THROUGH VIA :" at 83.561,88.244 h3
  text "PLUG THE VIAS WHICH ARE COVERED WITH SOLDERMASK ONE OR TWO SIDE." at 122.061,88.244 h3
  text "PLUG MATERIAL :" at 122.061,85.244 h3
  text "X  SOLDERMASK" at 147.561,85.244 h3
  text "NON-CONDUCTIVE EPOXY." at 172.811,85.244 h3
  text "H.   STACK-UP :" at 83.561,82.244 h3
  text "SEE LAYER STACK-UP SEQUENCE FOR OVERALL THICKNESS." at 122.061,82.244 h3
  text "MB1361C" at -8.8,78.9 h1.52
  text "Layer" at 87.229,70.2 h2
  text "Name" at 95.603,70.2 h2
  text "Material" at 111.8,70.2 h2
  text "Thickness" at 126.354,70.2 h2
  text "Constant" at 138.309,70.2 h2
  text "Board Layer Stack" at 149.373,70.2 h2
  text "1" at 87.229,66.2 h2
  text "Top Overlay" at 95.603,66.2 h2
  text "MINIMUN PARAMETERS" at 181.334,65.908 h3
  text "2" at 87.229,62.2 h2
  text "Top Solder" at 95.603,62.2 h2
  text "Solder Resist" at 111.8,62.2 h2
  text "0,015mm" at 126.354,62.2 h2
  text "3,5" at 138.309,62.2 h2
  text "DEFAULT" at 181.334,60.408 h3
  text "3" at 87.229,58.2 h2
  text "Top Layer" at 95.603,58.2 h2
  text "Copper" at 111.8,58.2 h2
  text "0,042mm" at 126.354,58.2 h2
  text "TRACKS : 0.127 mm           / GAPS : 0.127 mm" at 181.334,54.658 h3
  text "4" at 87.229,54.2 h2
  text "Dielectric 1" at 95.603,54.2 h2
  text "FR-4" at 111.8,54.2 h2
  text "0,100mm" at 126.354,54.2 h2
  text "4,2" at 138.309,54.2 h2
  text "5" at 87.229,50.2 h2
  text "Signal Layer 1" at 95.603,50.2 h2
  text "Copper" at 111.8,50.2 h2
  text "0,035mm" at 126.354,50.2 h2
  text "IMPEDANCE" at 181.434,49.508 h3
  text "6" at 87.229,46.2 h2
  text "Dielectric 2" at 95.603,46.2 h2
  text "0,102mm" at 126.354,46.2 h2
  text "4,2" at 138.309,46.2 h2
  text "TRACKS : 0.102 mm" at 181.3,45.7 h3
  text "7" at 87.229,42.2 h2
  text "Signal Layer 2" at 95.603,42.2 h2
  text "Copper" at 111.8,42.2 h2
  text "0,035mm" at 126.354,42.2 h2
  text "8" at 87.229,38.2 h2
  text "Dielectric 3" at 95.603,38.2 h2
  text "0,950mm" at 126.354,38.2 h2
  text "4,2" at 138.309,38.2 h2
  text "9" at 87.229,34.2 h2
  text "Signal Layer 3" at 95.603,34.2 h2
  text "Copper" at 111.8,34.2 h2
  text "0,035mm" at 126.354,34.2 h2
  text "10" at 87.229,30.2 h2
  text "Dielectric 4" at 95.603,30.2 h2
  text "0,102mm" at 126.354,30.2 h2
  text "4,2" at 138.309,30.2 h2
  text "11" at 87.229,26.2 h2
  text "Signal Layer 4" at 95.603,26.2 h2
  text "Copper" at 111.8,26.2 h2
  text "0,035mm" at 126.354,26.2 h2
  text "12" at 87.229,22.2 h2
  text "Dielectric 5" at 95.603,22.2 h2
  text "0,100mm" at 126.354,22.2 h2
  text "4,2" at 138.309,22.2 h2
  text "13" at 87.229,18.2 h2
  text "Bottom Layer" at 95.603,18.2 h2
  text "Copper" at 111.8,18.2 h2
  text "0,042mm" at 126.354,18.2 h2
  text "14" at 87.229,14.2 h2
  text "Bottom Solder" at 95.603,14.2 h2
  text "Solder Resist" at 111.8,14.2 h2
  text "0,015mm" at 126.354,14.2 h2
  text "3,5" at 138.309,14.2 h2
  text "15" at 87.229,10.2 h2
  text "Bottom Overlay" at 95.603,10.2 h2
  text "Symbol" at 84.592,-6.514 h2.4
  text "Count" at 93.991,-6.514 h2.4
  text "Hole Size" at 104.622,-6.514 h2.4
  text "Plated" at 123.893,-6.514 h2.4
  text "Drill Layer Pair" at 132.144,-6.514 h2.4
  text "Via/Pad" at 154.924,-6.514 h2.4
  text "Pad Shape" at 164.767,-6.514 h2.4
  text "Hole Length" at 177.625,-6.514 h2.4
  text "Routed Path Length" at 195.902,-6.514 h2.4
  text "2" at 93.991,-10.657 h2
  text "0,600mm (23,62mil)" at 104.622,-10.657 h2
  text "PTH" at 123.893,-10.657 h2
  text "Top Layer - Bottom Layer" at 132.144,-10.657 h2
  text "Pad" at 154.924,-10.657 h2
  text "Rounded" at 164.767,-10.657 h2
  text "1,300mm (51,18mil)" at 177.625,-10.657 h2
  text "0,700mm (27,56mil)" at 195.902,-10.657 h2
  text "2" at 93.991,-14.8 h2
  text "0,900mm (35,43mil)" at 104.622,-14.8 h2
  text "PTH" at 123.893,-14.8 h2
  text "Top Layer - Bottom Layer" at 132.144,-14.8 h2
  text "Pad" at 154.924,-14.8 h2
  text "Rounded" at 164.767,-14.8 h2
  text "-" at 177.625,-14.8 h2
  text "-" at 195.902,-14.8 h2
  text "4" at 93.991,-18.943 h2
  text "0,450mm (17,72mil)" at 104.622,-18.943 h2
  text "PTH" at 123.893,-18.943 h2
  text "Top Layer - Bottom Layer" at 132.144,-18.943 h2
  text "Pad" at 154.924,-18.943 h2
  text "Rounded" at 164.767,-18.943 h2
  text "0,850mm (33,47mil)" at 177.625,-18.943 h2
  text "0,400mm (15,75mil)" at 195.902,-18.943 h2
  text "5" at 93.991,-23.086 h2
  text "3,200mm (125,98mil)" at 104.622,-23.086 h2
  text "NPTH" at 123.893,-23.086 h2
  text "Top Layer - Bottom Layer" at 132.144,-23.086 h2
  text "Pad" at 154.924,-23.086 h2
  text "Rounded" at 164.767,-23.086 h2
  text "-" at 177.625,-23.086 h2
  text "-" at 195.902,-23.086 h2
  text "14" at 93.991,-27.229 h2
  text "0,400mm (15,75mil)" at 104.622,-27.229 h2
  text "PTH" at 123.893,-27.229 h2
  text "Top Layer - Bottom Layer" at 132.144,-27.229 h2
  text "Pad" at 154.924,-27.229 h2
  text "Rounded" at 164.767,-27.229 h2
  text "-" at 177.625,-27.229 h2
  text "-" at 195.902,-27.229 h2
  text "100" at 93.991,-31.372 h2
  text "1,100mm (43,31mil)" at 104.622,-31.372 h2
  text "PTH" at 123.893,-31.372 h2
  text "Top Layer - Bottom Layer" at 132.144,-31.372 h2
  text "Pad" at 154.924,-31.372 h2
  text "Rounded" at 164.767,-31.372 h2
  text "-" at 177.625,-31.372 h2
  text "-" at 195.902,-31.372 h2
  text "179" at 93.991,-35.515 h2
  text "1,000mm (39,37mil)" at 104.622,-35.515 h2
  text "PTH" at 123.893,-35.515 h2
  text "Top Layer - Bottom Layer" at 132.144,-35.515 h2
  text "Pad" at 154.924,-35.515 h2
  text "Rounded" at 164.767,-35.515 h2
  text "-" at 177.625,-35.515 h2
  text "-" at 195.902,-35.515 h2
  text "705" at 93.991,-39.659 h2
  text "0,200mm (7,87mil)" at 104.622,-39.659 h2
  text "PTH" at 123.893,-39.659 h2
  text "Top Layer - Bottom Layer" at 132.144,-39.659 h2
  text "Via" at 154.924,-39.659 h2
  text "Rounded" at 164.767,-39.659 h2
  text "-" at 177.625,-39.659 h2
  text "-" at 195.902,-39.659 h2
  text "1011 Total" at 93.991,-43.802 h2
  text "Slot definitions :" at 84.592,-46.702 h2
  text "Routed Path Length" at 98.245,-46.702 h2
  text "= Calculated from tool start centre position to tool end centre position." at 115.158,-46.702 h2
  text "Hole Length" at 98.245,-48.359 h2
  text "= Routed Path Length + Tool Size = Slot length as defined in the PCB layout" at 108.879,-48.359 h2
  text ".Layer_Name" at -11.916,-114.15 h3
  text ".DRL" at 29.778,-114.15 h3
M20-Top Sheet Box:
  circle w0.254: c66.088,-120.871 r1.3
  region: 51.61,-121.964 40.854,-121.964 41.847,-119.471 49.705,-119.471 50.153,-118.712 52.362,-121.26
  region: 65.613,-113.634 50.086,-113.634 49.391,-115.41 48.181,-116.634 46.784,-114.775 46.784,-113.124 47.927,-111.727 49.363,-111.348 65.613,-111.348
  lines w0.254: 41.847,-119.471 50.639,-119.471 47.573,-115.933 cw(c49.377,-113.989) 49.617,-111.348 66.381,-111.348 65.619,-113.634 ; 45.161,-111.101 cw(c47.587,-112.071) 47.823,-109.469 ; 45.2,-111.069 40.854,-121.964 60.176,-121.964 ccw(c60.425,-119.229) 62.974,-120.249 ; 46.94,-115.003 52.362,-121.26 ; 47.194,-115.003 52.499,-121.125 ; 47.194,-114.749 52.499,-120.871 ; 47.292,-113.634 60.285,-113.634 ; 47.321,-114.622 52.626,-120.744 ; 47.448,-114.495 52.753,-120.617 ; 47.575,-114.368 52.88,-120.49 ; 47.702,-114.241 53.007,-120.363 ; 47.756,-112.289 53.061,-118.41 ; 47.825,-109.469 67.274,-109.469 62.975,-120.247 ; 47.829,-114.114 53.079,-120.173 ; 47.829,-113.86 53.134,-119.982 ; 47.829,-113.606 53.134,-119.728 ; 47.829,-112.717 53.134,-118.839 ; 47.956,-113.479 53.261,-119.601 ; 47.956,-113.098 53.261,-119.22 ; 49.327,-119.484 ccw(c49.432,-118.949) 49.73,-118.492 ; 50.414,-113.621 ccw(c50.388,-114.188) 50.058,-114.65 52.423,-117.379 cw(c50.619,-119.323) 51.351,-121.871 ; 56.695,-121.76 59.585,-113.38 ; 56.918,-121.71 59.787,-113.389 ; 57.045,-121.71 59.914,-113.389 ; 57.299,-121.71 60.168,-113.389 ; 57.553,-121.71 60.422,-113.389 ; 57.807,-121.71 60.676,-113.389 ; 58.061,-121.71 60.93,-113.389 ; 58.315,-121.71 61.184,-113.389 ; 58.569,-121.71 61.438,-113.389 ; 58.823,-121.71 61.692,-113.389 ; 59.031,-121.76 61.921,-113.38 ; 61.921,-113.634 65.613,-113.634 ; 64.945,-113.632 65.707,-111.346 ; 65.111,-113.634 65.873,-111.348 ; 65.365,-113.634 66.127,-111.348
  lines w0.3: -20.917,-125.85 69.083,-125.85 69.083,-105.85 -20.917,-105.85 ; -20.917,-120.85 39.083,-120.85 ; -20.917,-115.85 39.083,-115.85 ; -20.917,-110.85 39.083,-110.85 ; -20.916,-125.85 -20.916,-105.85 ; 19.083,-125.85 19.083,-110.85 ; 39.083,-125.85 39.083,-105.85 ; 56.695,-121.76 59.031,-121.76
  text "Project: '.Board_Name'" at -19.916,-109.066 h3
  text "Layer:" at -19.916,-114.15 h3
  text "Gerber:" at 20.072,-114.15 h3
  text "Variant: '.VariantName'" at -19.916,-119.15 h3
  text "Ref: MB1361" at 20.199,-119.15 h3
  text "R" at 65.58,-121.633 h1.52
  text "Date: 19-FEB-21" at -19.916,-124.15 h3
  text "Rev: '.Board_PCB_Revision'" at 20.142,-124.15 h3
M21-Bottom Sheet Box:
  circle w0.254: c-17.734,-120.871 r1.3
  region: -17.259,-113.634 -1.732,-113.634 -1.038,-115.41 0.173,-116.634 1.57,-114.775 1.57,-113.124 0.427,-111.727 -1.009,-111.348 -17.259,-111.348
  region: -3.256,-121.964 7.5,-121.964 6.507,-119.471 -1.351,-119.471 -1.8,-118.712 -4.008,-121.26
  lines w0.254: -17.773,-111.348 -17.011,-113.634 ; -17.519,-111.348 -16.757,-113.634 ; -17.353,-111.346 -16.591,-113.632 ; -17.265,-113.634 -18.027,-111.348 -1.263,-111.348 cw(c-1.023,-113.989) 0.781,-115.933 -2.285,-119.471 6.507,-119.471 ; -17.259,-113.634 -13.567,-113.634 ; -14.621,-120.247 -18.921,-109.469 0.529,-109.469 ; -14.62,-120.249 ccw(c-12.071,-119.229) -11.822,-121.964 7.5,-121.964 3.154,-111.069 ; -13.567,-113.38 -10.677,-121.76 ; -13.338,-113.389 -10.469,-121.71 ; -13.084,-113.389 -10.215,-121.71 ; -12.83,-113.389 -9.961,-121.71 ; -12.576,-113.389 -9.707,-121.71 ; -12.322,-113.389 -9.453,-121.71 ; -12.068,-113.389 -9.199,-121.71 ; -11.931,-113.634 1.062,-113.634 ; -11.814,-113.389 -8.945,-121.71 ; -11.56,-113.389 -8.691,-121.71 ; -11.433,-113.389 -8.564,-121.71 ; -11.231,-113.38 -8.341,-121.76 ; -4.907,-119.601 0.398,-113.479 ; -4.907,-119.22 0.398,-113.098 ; -4.78,-119.982 0.525,-113.86 ; -4.78,-119.728 0.525,-113.606 ; -4.78,-118.839 0.525,-112.717 ; -4.725,-120.173 0.525,-114.114 ; -4.708,-118.41 0.597,-112.289 ; -4.653,-120.363 0.652,-114.241 ; -4.526,-120.49 0.779,-114.368 ; -4.399,-120.617 0.906,-114.495 ; -4.272,-120.744 1.033,-114.622 ; -4.145,-121.125 1.16,-115.003 ; -4.145,-120.871 1.16,-114.749 ; -4.008,-121.26 1.414,-115.003 ; -2.997,-121.871 cw(c-2.265,-119.323) -4.069,-117.379 -1.704,-114.65 ccw(c-2.034,-114.188) -2.06,-113.621 ; -1.376,-118.492 ccw(c-1.079,-118.949) -0.974,-119.484 ; 0.53,-109.469 cw(c0.767,-112.071) 3.193,-111.101
  lines w0.3: -10.677,-121.76 -8.341,-121.76 ; 9.083,-125.85 9.083,-105.85 ; 9.083,-120.85 69.083,-120.85 ; 9.083,-115.85 69.083,-115.85 ; 9.083,-110.85 69.083,-110.85 ; 29.083,-125.85 29.083,-110.85 ; -20.917,-125.85 -20.917,-105.85 69.083,-105.85 69.083,-125.85 -20.917,-125.85
  text "Project: '.Board_Name'" at 67.889,-109.066 h3
  text "Gerber:" at 27.901,-114.15 h3
  text "Layer:" at 67.889,-114.15 h3
  text "Ref: MB1361" at 27.901,-119.15 h3
  text "Variant: '.VariantName'" at 67.889,-119.15 h3
  text "R" at -17.226,-121.633 h1.52
  text "Rev: '.Board_PCB_Revision'" at 27.958,-124.15 h3
  text "Date: 19-FEB-21" at 67.889,-124.15 h3

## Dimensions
57.13,77.46 to 57.126,-55.881 on M2-Board Dimensions
-10.87,-53.88 to 59.13,-53.88 on M2-Board Dimensions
